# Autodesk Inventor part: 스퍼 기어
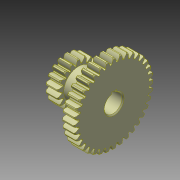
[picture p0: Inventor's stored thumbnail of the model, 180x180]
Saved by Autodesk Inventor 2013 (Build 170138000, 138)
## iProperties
Created: 2024-01
Part Number: 스퍼 기어
Material: 강철, 탄소
Document SubType Name: Modeling
Designer: mdu-01
Density: 1 g/cm^3
Author: mdu-01
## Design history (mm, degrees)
sketch "스케치1"
  geometry: L1 (0, 0)-(46, 0); L2 (46, 9.5)-(46, 33.5); L3 (46, 33.5)-(34, 33.5); L4 (34, 33.5)-(34, 14); L5 (34, 14)-(12, 14); L6 (12, 14)-(12, 15.5); L7 (12, 15.5)-(0, 15.5); L8 (0, 15.5)-(0, 9.5); L9 (1, 8.5)-(45, 8.5); L10 (0, 9.5)-(1, 8.5); L11 (46, 9.5)-(45, 8.5); 4 further points
  constraints: 22 end point, 7 parallel, 7 point on line, 2 perpendicular, 1 horizontal
  dimensions: "d0" = 46 distance between parallel lines of L2 L8; "d2" = 36 diameter of point (0, 18) L1; "d3" = 2.5 distance from line of L7 point (0, 18); "d4" = 12 distance between parallel lines of L6 L8; "d5" = 28 diameter of L5 L1; "d6" = 17 diameter of L9 L1; "d7" = 72 diameter of point (46, 36) L1; "d9" = 2.5 distance from line of L3 point (46, 36); "d10" = 1 distance of L8.end point (0, 8.5); "d11" = 1 distance of L9.start point (0, 8.5) (= d10); "d12" = 1 distance of L2.start point (46, 8.5) (= d10); "d13" = 1 distance of L9.end point (46, 8.5) (= d12)
revolve "회전1" sketch "스케치1" stored, may be unused: angle "d14" = 90 deg
sketch "스케치2" dims "d15" = 2.5
  geometry: L1 (0, 0)-(0, 20); A1 r 20 centre (0, 0) between (0.57, 19.992) and (-0.57, 19.992); A2 r 9.478 centre (-7.394, 14.854) between (2.07, 15.361) and (0.57, 19.992); A3 r 9.478 centre (7.394, 14.854) between (-0.57, 19.992) and (-2.07, 15.361); A4 r 15.5 centre (0, 0) between (2.07, 15.361) and (-2.07, 15.361); 2 further points
  constraints: 10 point on circle, 4 centre point, 3 symmetric about line, 2 end point, 1 coincident, 1 vertical, 6 other
  dimensions: "d16" = 2 dimension on A1; "d17" = 1.57 distance from line of point (1.57, 17.931) L1; "d18" = 1 horizontal distance of A1.start point (1.57, 17.931); "d19" = 0.5 horizontal distance of A2.start point (1.57, 17.931)
extrude "돌출1" join sketch "스케치2" stored distance "d20" = 10; taper "d21" = 0 deg
chamfer "모따기1" distance "d22" = 1; stored, may be unused: second distance "d23" = 2, angle "d24" = 45 deg
fillet "모깎기1" dims "d25" = 0.25
sketch "스케치3" dims "d29" = 2.5
  geometry: L1 (0, 0)-(0, 38); A1 r 38 centre (0, 0) between (0.57, 37.996) and (-0.57, 37.996); A2 r 9.246 centre (-7.162, 32.926) between (2.07, 33.436) and (0.57, 37.996); A3 r 9.246 centre (7.162, 32.926) between (-0.57, 37.996) and (-2.07, 33.436); A4 r 33.5 centre (0, 0) between (2.07, 33.436) and (-2.07, 33.436); 2 further points
  constraints: 10 point on circle, 4 centre point, 3 symmetric about line, 2 coincident, 2 end point, 1 vertical, 6 other
  dimensions: "d30" = 2 dimension on A1; "d31" = 1.57 distance from line of point (1.57, 35.966) L1; "d32" = 0.5 horizontal distance of A2.start point (1.57, 35.966); "d33" = 1 horizontal distance of A1.start point (1.57, 35.966)
extrude "돌출2" join sketch "스케치3" stored distance "d34" = 0; taper "d35" = 0 deg
chamfer "모따기2" distance "d36" = 1; stored, may be unused: second distance "d37" = 2, angle "d38" = 45 deg
fillet "모깎기2" dims "d39" = 0.25
sketch "스케치4"
  geometry: L1 (-2.5, 8.124)-(2.5, 8.124); L2 (2.5, 8.124)-(2.5, 10.8); L3 (2.5, 10.8)-(-2.5, 10.8); L4 (-2.5, 10.8)-(-2.5, 8.124); A1 r 8.5 centre (0, 0) between (-2.5, 8.124) and (2.5, 8.124) reference; 2 further points
  constraints: 8 end point, 3 point on circle, 2 parallel, 1 horizontal, 1 perpendicular, 1 vertical alignment
  dimensions: "d43" = 5 distance between parallel lines of L2 L4; "d45" = 19.3 distance from line of point (0, -8.5) L3
extrude "돌출3" cut sketch "스케치4" stored distance "d46" = 10; taper "d47" = 0 deg
node "솔리드1"
pattern_circular "원형 패턴1" dims "d27" = 360 deg
pattern_circular "원형 패턴2" dims "d41" = 360 deg
